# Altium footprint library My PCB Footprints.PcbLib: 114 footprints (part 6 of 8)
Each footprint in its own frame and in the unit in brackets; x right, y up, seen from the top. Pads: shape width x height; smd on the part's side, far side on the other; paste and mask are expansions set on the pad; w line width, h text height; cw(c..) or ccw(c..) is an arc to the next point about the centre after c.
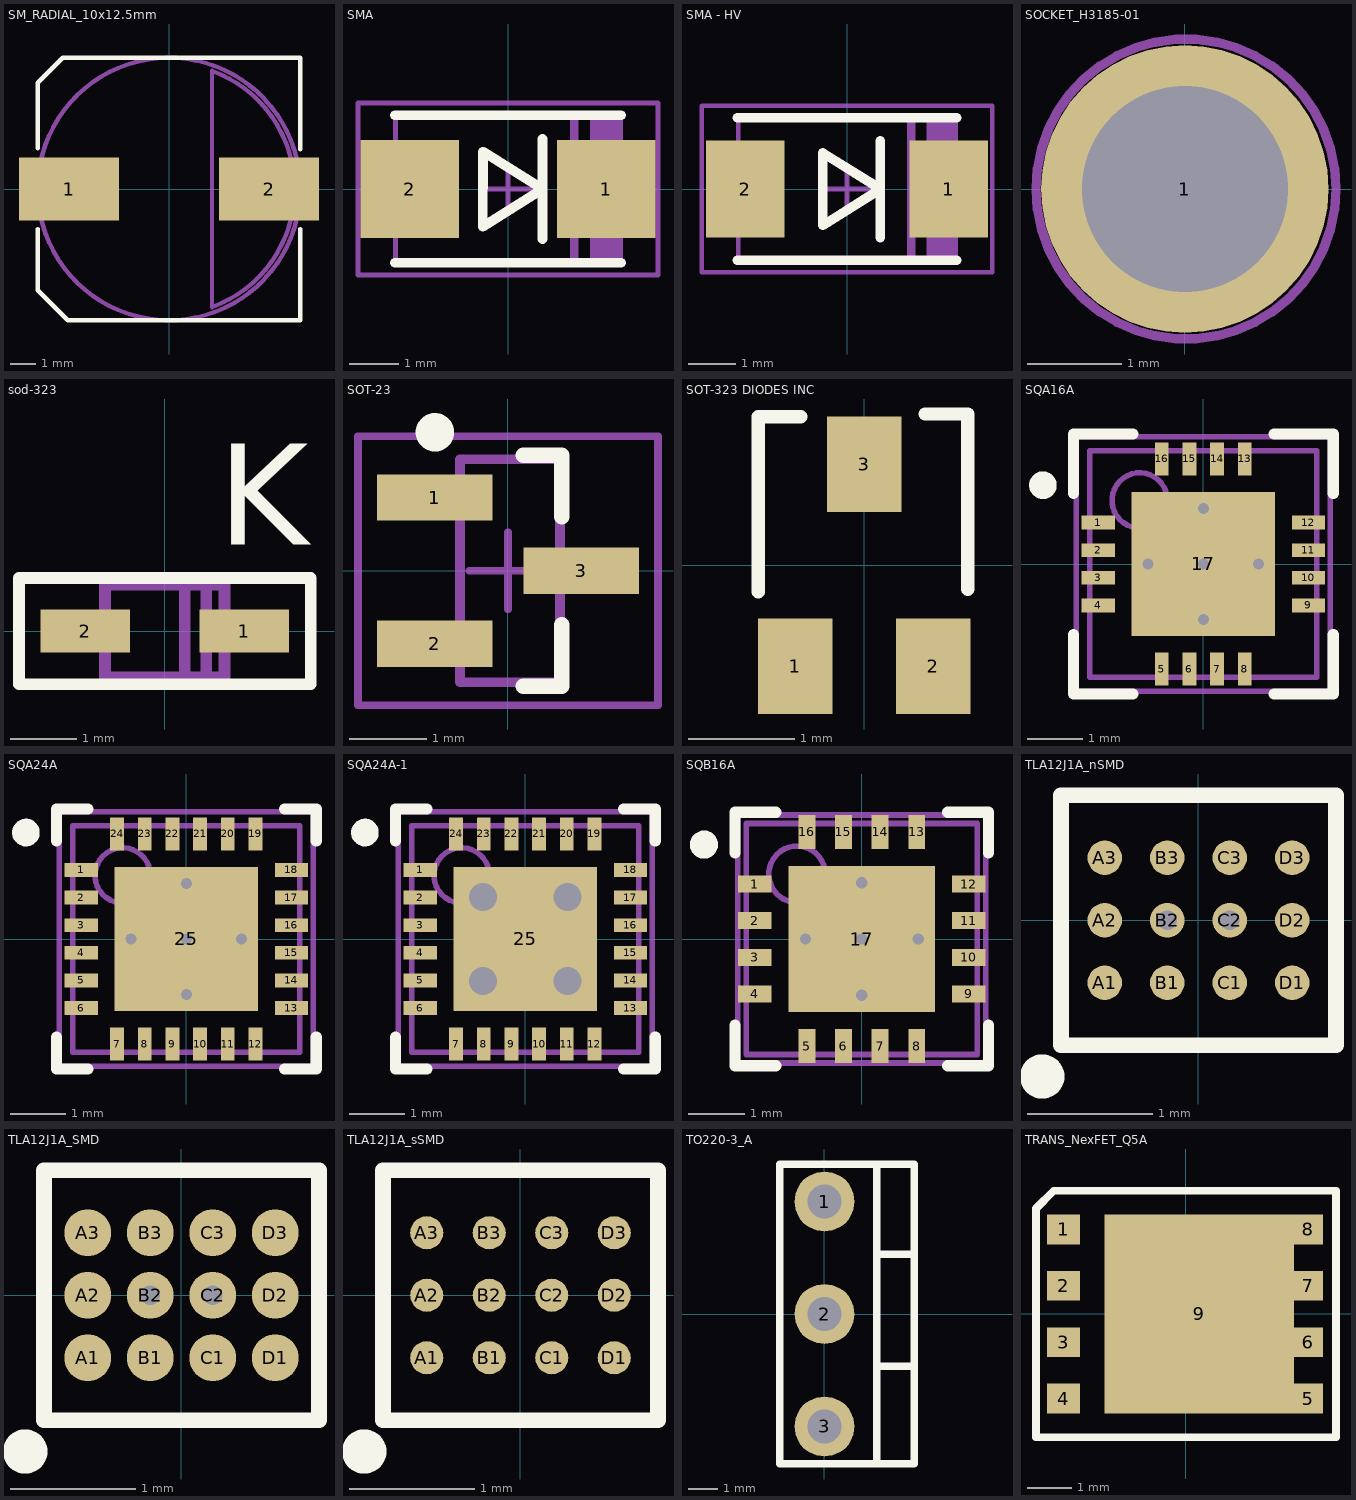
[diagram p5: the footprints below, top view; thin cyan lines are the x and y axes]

## SM_RADIAL_10x12.5mm [mm] "Suncon 10x12.5"
height 12.5
pads (2):
  rect 4x2.5 smd: 1(-4,0) 2(4,0)
Top Overlay:
  lines w0.178: -5.25,-1.6 -5.25,-4.046 -4.046,-5.25 5.25,-5.25 5.25,-1.6 ; -5.25,1.624 -5.25,4.25 -4.25,5.25 5.25,5.25 5.25,1.597
Mechanical 5:
  text ".Designator" at -1.524,-0.508 h1.02
Mechanical 13:
  circle w0.178: c0,0 r5.25
  lines w0.178: 1.72,-4.725 ccw(c0,0) 1.72,4.725 1.72,-4.725
3D body: height 1, standoff 0, extent -5.251,-5.251 5.251,5.251
3D body: height 12.5, standoff 1, extent -5.261,-5.261 5.261,5.261
3D body: height 10.5, standoff 10.4, extent 1.719,-4.726 5.039,4.726

## SMA [mm] "Molded Diode, 2-Leads, Body 4.3x2.6mm, IPC Medium Density, based on OnSemi component dimensions and land pattern"
height 2.27
pads (2):
  rect 2x2 smd: 1(2,0) 2(-2,0)
Top Overlay:
  lines w0.2: -2.3,-1.5 2.3,-1.5 ; -2.3,1.5 2.3,1.5 ; 0.698,-0.004 -0.512,-0.766 -0.507,0.758 0.698,0.006
  lines w0.203: 0.698,-1.022 0.698,1.016
Mechanical 5:
  text ".designator" at -0.927,-0.518 h1.02
Mechanical 13:
  rectangle: 1.67,-1.46 2.285,1.46
  lines w0.1: -2.285,-1.46 2.285,-1.46 2.285,1.46 -2.285,1.46 -2.285,-1.46
  lines w0.178: 1.346,-1.46 1.346,1.46 ; 1.905,-1.46 1.905,1.46
Mechanical 15:
  lines w0.1: -0.5,0 0.5,0 ; 0,-0.5 0,0.5 ; -3.05,-1.75 3.05,-1.75 3.05,1.75 -3.05,1.75 -3.05,-1.75
3D body: height 2.27, standoff 0, extent -2.285,-1.46 2.285,1.46
3D body: height 2.27, standoff 2.2, extent 1.347,-1.459 1.904,1.459

## SMA - HV [mil] "Molded Diode, 2-Leads, Body 4.3x2.6mm. Based on STTH1R06 footprint dimensions and land pattern for 600V."
height 89.37
pads (2):
  rect 65x80 smd: 1(84,0) 2(-84,0)
Top Overlay:
  lines w7.87: -90.55,-59.06 90.55,-59.06 ; -90.55,59.06 90.55,59.06 ; 27.48,-0.15 -20.16,-30.16 -19.97,29.85 27.48,0.22
  lines w8: 27.48,-40.22 27.48,40
Mechanical 5:
  text ".designator" at -36.5,-20.4 h40
Mechanical 13:
  rectangle: 65.76,-57.48 89.96,57.48
  lines w3.94: -89.96,-57.48 -89.96,57.48 89.96,57.48 89.96,-57.48 -89.96,-57.48
  lines w7: 53,-57.48 53,57.48 ; 75,-57.48 75,57.48
Mechanical 15:
  lines w3.94: -19.69,0 19.68,0 ; 0,-19.68 0,19.69 ; -120.08,-68.9 -120.08,68.9 120.08,68.9 120.08,-68.9 -120.08,-68.9
3D body: height 89.37, standoff 86.61, extent 53.02,-57.46 74.98,57.46
3D body: height 89.37, standoff 0, extent -89.96,-57.48 89.96,57.48

## SOCKET_H3185-01 [mil] "Socket pin, 1 mm Diameter"
height 39.37
pads (1):
  round 120 hole 86: 1(0,0)
Mechanical 5:
  circle w3.94: c0.5,0 r62.6
  text ".Designator" at -37,-10 h20
3D body: height 39.37, standoff -196.85, extent -62.1,-62.47 62.6,62.48

## sod-323 [mm] "Diodes Inc recommended land pattern"
height 1.5
pads (2):
  rect 1.35x0.65 smd: 1(1.2,0) 2(-1.2,0)
Top Overlay:
  lines w0.178: -2.2,-0.8 0,-0.8 2.2,-0.8 2.2,0 2.2,0.8 0,0.8 -2.2,0.8 -2.2,0 -2.2,-0.8
  text "K" at 0.8,1.3 h1.52
Mechanical 5:
  text ".Designator" at -1.524,-0.508 h1.02
Mechanical 13:
  lines w0.178: 0.3,-0.701 0.3,0.699 ; 0.625,-0.701 0.625,0.699 ; -0.902,-0.701 0.898,-0.701 0.898,0.699 -0.902,0.699 -0.902,-0.701
3D body: height 1.5, standoff 0, extent -0.901,-0.701 0.898,0.698
3D body: height 1.5, standoff 1.5, extent 0.301,-0.701 0.624,0.698

## SOT-23 [mm] "SOT23, 3-Leads, Body 2.9x1.3mm, Pitch 0.95mm, Lead Span 2.5mm, IPC Medium Density"
height 1.1
pads (3):
  rect 1.5x0.6 smd: 1(-0.95,0.95) 2(-0.95,-0.95) 3(0.95,0)
Top Overlay:
  circle w0.25: c-0.95,1.8 r0.125
  lines w0.2: 0.2,-1.5 0.7,-1.5 0.7,-0.7 ; 0.2,1.5 0.7,1.5 0.7,0.7
Mechanical 5:
  lines w0.127: -1.16,-1.15 -0.625,-1.15 -0.625,-1.45 0.675,-1.45 0.675,-0.2 1.21,-0.2 1.21,0.2 0.675,0.2 0.675,1.45 -0.625,1.45 -0.625,1.15 -1.16,1.15 -1.16,0.75 -0.625,0.75 -0.625,-0.75 -1.16,-0.75 -1.16,-1.15
  text ".Designator" at -0.175,1.225 h0.64
Mechanical 15:
  lines w0.1: -0.5,0 0.5,0 ; 0,-0.5 0,0.5 ; -1.95,-1.75 -1.95,1.75 1.95,1.75 1.95,-1.75 -1.95,-1.75
3D body: height 1, standoff 0, extent -1.16,-1.45 1.21,1.45

## SOT-323 DIODES INC [mm] "SOT-323 DIODES INC"
height 1.016
pads (4):
  round 0.25 on Top Overlay: 0(-1.3,-0.95)
  rect 0.7x0.9 smd: 1(-0.65,-0.95) 2(0.65,-0.95) 3(0,0.95)
Top Overlay:
  lines w0.127: -1,-0.25 -1,1.397 -0.6,1.397 ; 0.575,1.425 0.975,1.425 0.975,-0.225
Mechanical 5:
  text ".Designator" at 0,0 h1.52
3D body: height 1, standoff 0, extent -1,-1.45 0.975,1.5

## SQA16A [mm] "QFN, 16-Leads, Body 4x4mm, Pitch 0.5mm, NSC Recommended"
height 0.8
pads (17):
  rect 0.6x0.25 smd paste-0.125 mask+0.051: 1(-1.9,0.75) 2(-1.9,0.25) 3(-1.9,-0.25) 4(-1.9,-0.75) 9(1.9,-0.75) 10(1.9,-0.25) 11(1.9,0.25) 12(1.9,0.75)
  rect 0.25x0.6 smd paste-0.125 mask+0.051: 5(-0.75,-1.9) 6(-0.25,-1.9) 7(0.25,-1.9) 8(0.75,-1.9) 13(0.75,1.9) 14(0.25,1.9) 15(-0.25,1.9) 16(-0.75,1.9)
  rect 2.6x2.6 smd paste-1.3 mask+0.051: 17(0,0)
via 0,0 diameter 0.5 hole 0.2
via 1,0 diameter 0.5 hole 0.2
via -1,0 diameter 0.5 hole 0.2
via 0,1 diameter 0.5 hole 0.2
via 0,-1 diameter 0.5 hole 0.2
Top Overlay:
  circle w0.25: c-2.9,1.425 r0.125
  lines w0.2: -2.35,-1.275 -2.35,-2.35 -1.275,-2.35 ; -2.35,1.275 -2.35,2.35 -1.275,2.35 ; 1.275,-2.35 2.35,-2.35 2.35,-1.275 ; 1.275,2.35 2.35,2.35 2.35,1.275
Top Paste:
  region: -0.625,-2.4 -0.625,-1.7 -0.875,-1.7 -0.875,-2.4
  region: -0.125,-2.4 -0.125,-1.7 -0.375,-1.7 -0.375,-2.4
  region: 0.375,-2.4 0.375,-1.7 0.125,-1.7 0.125,-2.4
  region: 0.875,-2.4 0.875,-1.7 0.625,-1.7 0.625,-2.4
  region: 0.625,2.4 0.625,1.7 0.875,1.7 0.875,2.4
  region: 0.125,2.4 0.125,1.7 0.375,1.7 0.375,2.4
  region: -0.375,2.4 -0.375,1.7 -0.125,1.7 -0.125,2.4
  region: -0.875,2.4 -0.875,1.7 -0.625,1.7 -0.625,2.4
  region: 2.4,-0.625 1.7,-0.625 1.7,-0.875 2.4,-0.875
  region: 2.4,-0.125 1.7,-0.125 1.7,-0.375 2.4,-0.375
  region: 2.4,0.375 1.7,0.375 1.7,0.125 2.4,0.125
  region: 2.4,0.875 1.7,0.875 1.7,0.625 2.4,0.625
  rectangle: -2.4,-0.875 -1.7,-0.625
  rectangle: -2.4,-0.375 -1.7,-0.125
  rectangle: -2.4,0.125 -1.7,0.375
  rectangle: -2.4,0.625 -1.7,0.875
  rectangle: 0.1,0.1 1.2,1.2
  region: -0.1,1.2 -1.2,1.2 -1.2,0.1 -0.1,0.1
  region: -0.1,-0.1 -1.2,-0.1 -1.2,-1.2 -0.1,-1.2
  rectangle: 0.1,-1.2 1.2,-0.1
Mechanical 5:
  text ".Designator" at -1.524,-0.508 h1.02
Mechanical 13:
  circle w0.1: c-1.15,1.15 r0.5
  lines w0.1: -2.05,-2.05 2.05,-2.05 2.05,2.05 -2.05,2.05 -2.05,-2.05
Mechanical 15:
  lines w0.1: -0.5,0 0.5,0 ; 0,-0.5 0,0.5 ; -2.3,-2.3 2.3,-2.3 2.3,2.3 -2.3,2.3 -2.3,-2.3
3D body: height 0.8, standoff 0, extent -2.05,-2.05 2.05,2.05

## SQA24A [mm] "QFN, 24-Leads, Body 4x4mm, Pitch 0.5mm, NSC Recommended"
height 0.8
pads (25):
  rect 0.6x0.25 smd paste-0.125 mask+0.051: 1(-1.9,1.25) 2(-1.9,0.75) 3(-1.9,0.25) 4(-1.9,-0.25) 5(-1.9,-0.75) 6(-1.9,-1.25) 13(1.9,-1.25) 14(1.9,-0.75) 15(1.9,-0.25) 16(1.9,0.25) 17(1.9,0.75) 18(1.9,1.25)
  rect 0.25x0.6 smd paste-0.125 mask+0.051: 7(-1.25,-1.9) 8(-0.75,-1.9) 9(-0.25,-1.9) 10(0.25,-1.9) 11(0.75,-1.9) 12(1.25,-1.9) 19(1.25,1.9) 20(0.75,1.9) 21(0.25,1.9) 22(-0.25,1.9) 23(-0.75,1.9) 24(-1.25,1.9)
  rect 2.6x2.6 smd paste-1.3 mask+0.051: 25(0,0)
via 0,0 diameter 0.5 hole 0.2
via 1,0 diameter 0.5 hole 0.2
via -1,0 diameter 0.5 hole 0.2
via 0,1 diameter 0.5 hole 0.2
via 0,-1 diameter 0.5 hole 0.2
Top Overlay:
  circle w0.25: c-2.9,1.925 r0.125
  lines w0.2: -2.35,-1.775 -2.35,-2.35 -1.775,-2.35 ; -2.35,1.775 -2.35,2.35 -1.775,2.35 ; 1.775,-2.35 2.35,-2.35 2.35,-1.775 ; 1.775,2.35 2.35,2.35 2.35,1.775
Top Paste:
  region: 1.125,2.4 1.125,1.7 1.375,1.7 1.375,2.4
  region: 0.625,2.4 0.625,1.7 0.875,1.7 0.875,2.4
  region: 0.125,2.4 0.125,1.7 0.375,1.7 0.375,2.4
  region: -0.375,2.4 -0.375,1.7 -0.125,1.7 -0.125,2.4
  region: -0.875,2.4 -0.875,1.7 -0.625,1.7 -0.625,2.4
  region: -1.375,2.4 -1.375,1.7 -1.125,1.7 -1.125,2.4
  region: 2.4,-1.125 1.7,-1.125 1.7,-1.375 2.4,-1.375
  region: 2.4,-0.625 1.7,-0.625 1.7,-0.875 2.4,-0.875
  region: 2.4,-0.125 1.7,-0.125 1.7,-0.375 2.4,-0.375
  region: 2.4,0.375 1.7,0.375 1.7,0.125 2.4,0.125
  region: 2.4,0.875 1.7,0.875 1.7,0.625 2.4,0.625
  region: 2.4,1.375 1.7,1.375 1.7,1.125 2.4,1.125
  region: -1.125,-2.4 -1.125,-1.7 -1.375,-1.7 -1.375,-2.4
  region: -0.625,-2.4 -0.625,-1.7 -0.875,-1.7 -0.875,-2.4
  region: -0.125,-2.4 -0.125,-1.7 -0.375,-1.7 -0.375,-2.4
  region: 0.375,-2.4 0.375,-1.7 0.125,-1.7 0.125,-2.4
  region: 0.875,-2.4 0.875,-1.7 0.625,-1.7 0.625,-2.4
  region: 1.375,-2.4 1.375,-1.7 1.125,-1.7 1.125,-2.4
  rectangle: -2.4,-1.375 -1.7,-1.125
  rectangle: -2.4,-0.875 -1.7,-0.625
  rectangle: -2.4,-0.375 -1.7,-0.125
  rectangle: -2.4,0.125 -1.7,0.375
  rectangle: -2.4,0.625 -1.7,0.875
  rectangle: -2.4,1.125 -1.7,1.375
  rectangle: 0.1,-1.2 1.2,-0.1
  region: -0.1,-0.1 -1.2,-0.1 -1.2,-1.2 -0.1,-1.2
  region: -0.1,1.2 -1.2,1.2 -1.2,0.1 -0.1,0.1
  rectangle: 0.1,0.1 1.2,1.2
Mechanical 5:
  text ".Designator" at -1.524,-0.508 h1.02
Mechanical 13:
  circle w0.1: c-1.15,1.15 r0.5
  lines w0.1: -2.05,-2.05 -2.05,2.05 2.05,2.05 2.05,-2.05 -2.05,-2.05
Mechanical 15:
  lines w0.1: -0.5,0 0.5,0 ; 0,-0.5 0,0.5 ; -2.3,-2.3 -2.3,2.3 2.3,2.3 2.3,-2.3 -2.3,-2.3
3D body: height 0.8, standoff 0, extent -2.05,-2.05 2.05,2.05

## SQA24A-1 [mm] "QFN, 24-Leads, Body 4x4mm, Pitch 0.5mm, 4 x 20mil vias"
height 0.8
pads (25):
  rect 0.6x0.25 smd paste-0.125 mask+0.051: 1(-1.9,1.25) 2(-1.9,0.75) 3(-1.9,0.25) 4(-1.9,-0.25) 5(-1.9,-0.75) 6(-1.9,-1.25) 13(1.9,-1.25) 14(1.9,-0.75) 15(1.9,-0.25) 16(1.9,0.25) 17(1.9,0.75) 18(1.9,1.25)
  rect 0.25x0.6 smd paste-0.125 mask+0.051: 7(-1.25,-1.9) 8(-0.75,-1.9) 9(-0.25,-1.9) 10(0.25,-1.9) 11(0.75,-1.9) 12(1.25,-1.9) 19(1.25,1.9) 20(0.75,1.9) 21(0.25,1.9) 22(-0.25,1.9) 23(-0.75,1.9) 24(-1.25,1.9)
  rect 2.6x2.6 smd paste-1.3 mask+0.051: 25(0,0)
via -0.762,-0.762 diameter 0.965 hole 0.508
via 0.762,0.762 diameter 0.965 hole 0.508
via -0.762,0.762 diameter 0.965 hole 0.508
via 0.762,-0.762 diameter 0.965 hole 0.508
Top Overlay:
  circle w0.25: c-2.9,1.925 r0.125
  lines w0.2: -2.35,-1.775 -2.35,-2.35 -1.775,-2.35 ; -2.35,1.775 -2.35,2.35 -1.775,2.35 ; 1.775,-2.35 2.35,-2.35 2.35,-1.775 ; 1.775,2.35 2.35,2.35 2.35,1.775
Top Paste:
  region: 1.125,2.4 1.125,1.7 1.375,1.7 1.375,2.4
  region: 0.625,2.4 0.625,1.7 0.875,1.7 0.875,2.4
  region: 0.125,2.4 0.125,1.7 0.375,1.7 0.375,2.4
  region: -0.375,2.4 -0.375,1.7 -0.125,1.7 -0.125,2.4
  region: -0.875,2.4 -0.875,1.7 -0.625,1.7 -0.625,2.4
  region: -1.375,2.4 -1.375,1.7 -1.125,1.7 -1.125,2.4
  region: 2.4,-1.125 1.7,-1.125 1.7,-1.375 2.4,-1.375
  region: 2.4,-0.625 1.7,-0.625 1.7,-0.875 2.4,-0.875
  region: 2.4,-0.125 1.7,-0.125 1.7,-0.375 2.4,-0.375
  region: 2.4,0.375 1.7,0.375 1.7,0.125 2.4,0.125
  region: 2.4,0.875 1.7,0.875 1.7,0.625 2.4,0.625
  region: 2.4,1.375 1.7,1.375 1.7,1.125 2.4,1.125
  region: -1.125,-2.4 -1.125,-1.7 -1.375,-1.7 -1.375,-2.4
  region: -0.625,-2.4 -0.625,-1.7 -0.875,-1.7 -0.875,-2.4
  region: -0.125,-2.4 -0.125,-1.7 -0.375,-1.7 -0.375,-2.4
  region: 0.375,-2.4 0.375,-1.7 0.125,-1.7 0.125,-2.4
  region: 0.875,-2.4 0.875,-1.7 0.625,-1.7 0.625,-2.4
  region: 1.375,-2.4 1.375,-1.7 1.125,-1.7 1.125,-2.4
  rectangle: -2.4,-1.375 -1.7,-1.125
  rectangle: -2.4,-0.875 -1.7,-0.625
  rectangle: -2.4,-0.375 -1.7,-0.125
  rectangle: -2.4,0.125 -1.7,0.375
  rectangle: -2.4,0.625 -1.7,0.875
  rectangle: -2.4,1.125 -1.7,1.375
  rectangle: 0.1,-1.2 1.2,-0.1
  region: -0.1,-0.1 -1.2,-0.1 -1.2,-1.2 -0.1,-1.2
  region: -0.1,1.2 -1.2,1.2 -1.2,0.1 -0.1,0.1
  rectangle: 0.1,0.1 1.2,1.2
Mechanical 5:
  text ".Designator" at -1.524,-0.508 h1.02
Mechanical 13:
  circle w0.1: c-1.15,1.15 r0.5
  lines w0.1: -2.05,-2.05 -2.05,2.05 2.05,2.05 2.05,-2.05 -2.05,-2.05
Mechanical 15:
  lines w0.1: -0.5,0 0.5,0 ; 0,-0.5 0,0.5 ; -2.3,-2.3 -2.3,2.3 2.3,2.3 2.3,-2.3 -2.3,-2.3
3D body: height 0.8, standoff 0, extent -2.05,-2.05 2.05,2.05

## SQB16A [mm] "QFN, 16-Leads, Body 4x4mm, Pitch 0.65mm, NSC Recommended"
height 0.8
pads (17):
  rect 0.6x0.3 smd paste-0.15 mask+0.051: 1(-1.9,0.975) 2(-1.9,0.325) 3(-1.9,-0.325) 4(-1.9,-0.975) 9(1.9,-0.975) 10(1.9,-0.325) 11(1.9,0.325) 12(1.9,0.975)
  rect 0.3x0.6 smd paste-0.15 mask+0.051: 5(-0.975,-1.9) 6(-0.325,-1.9) 7(0.325,-1.9) 8(0.975,-1.9) 13(0.975,1.9) 14(0.325,1.9) 15(-0.325,1.9) 16(-0.975,1.9)
  rect 2.6x2.6 smd paste-1.3 mask+0.051: 17(0,0)
via 0,0 diameter 0.5 hole 0.2
via 1,0 diameter 0.5 hole 0.2
via -1,0 diameter 0.5 hole 0.2
via 0,1 diameter 0.5 hole 0.2
via 0,-1 diameter 0.5 hole 0.2
Top Overlay:
  circle w0.25: c-2.8,1.675 r0.125
  lines w0.2: -2.25,-1.525 -2.25,-2.25 -1.525,-2.25 ; -2.25,1.525 -2.25,2.25 -1.525,2.25 ; 1.525,-2.25 2.25,-2.25 2.25,-1.525 ; 1.525,2.25 2.25,2.25 2.25,1.525
Top Paste:
  rectangle: -2.4,0.825 -1.7,1.125
  rectangle: -2.4,0.175 -1.7,0.475
  rectangle: -2.4,-0.475 -1.7,-0.175
  rectangle: -2.4,-1.125 -1.7,-0.825
  region: 1.125,-2.4 1.125,-1.7 0.825,-1.7 0.825,-2.4
  region: 0.475,-2.4 0.475,-1.7 0.175,-1.7 0.175,-2.4
  region: -0.175,-2.4 -0.175,-1.7 -0.475,-1.7 -0.475,-2.4
  region: -0.825,-2.4 -0.825,-1.7 -1.125,-1.7 -1.125,-2.4
  region: 2.4,1.125 1.7,1.125 1.7,0.825 2.4,0.825
  region: 2.4,0.475 1.7,0.475 1.7,0.175 2.4,0.175
  region: 2.4,-0.175 1.7,-0.175 1.7,-0.475 2.4,-0.475
  region: 2.4,-0.825 1.7,-0.825 1.7,-1.125 2.4,-1.125
  region: -1.125,2.4 -1.125,1.7 -0.825,1.7 -0.825,2.4
  region: -0.475,2.4 -0.475,1.7 -0.175,1.7 -0.175,2.4
  region: 0.175,2.4 0.175,1.7 0.475,1.7 0.475,2.4
  region: 0.825,2.4 0.825,1.7 1.125,1.7 1.125,2.4
  rectangle: 0.1,0.1 1.2,1.2
  region: -0.1,1.2 -1.2,1.2 -1.2,0.1 -0.1,0.1
  region: -0.1,-0.1 -1.2,-0.1 -1.2,-1.2 -0.1,-1.2
  rectangle: 0.1,-1.2 1.2,-0.1
Mechanical 5:
  text ".Designator" at -1.524,-0.508 h1.02
Mechanical 13:
  circle w0.1: c-1.15,1.15 r0.5
  lines w0.1: -2.05,-2.05 -2.05,2.05 2.05,2.05 2.05,-2.05 -2.05,-2.05
Mechanical 15:
  lines w0.1: -0.5,0 0.5,0 ; 0,-0.5 0,0.5 ; -2.2,-2.2 -2.2,2.2 2.2,2.2 2.2,-2.2 -2.2,-2.2
3D body: height 0.8, standoff 0, extent -2.05,-2.05 2.05,2.05

## TLA12J1A_nSMD [mm] "12 Bump µSMD,  non-Solder Mask Defined, 2 x 2mm"
height 0.675
pads (12):
  round 0.275 smd: A1(-0.75,-0.5) A2(-0.75,0) A3(-0.75,0.5) B1(-0.25,-0.5) B2(-0.25,0) B3(-0.25,0.5) C1(0.25,-0.5) C2(0.25,0) C3(0.25,0.5) D1(0.75,-0.5) D2(0.75,0) D3(0.75,0.5)
via 0.25,0 diameter 0.275 hole 0.152
via -0.25,0 diameter 0.275 hole 0.152
Top Overlay:
  circle w0.254: c-1.25,-1.25 r0.05
  lines w0.127: -1.1,-1 1.1,-1 1.1,1 -1.1,1 -1.1,-1
Mechanical 5:
  text ".Designator" at -1.35,-0.35 h1.02
3D body: height 0.67, standoff 0, extent -1,-0.9 1,0.9

## TLA12J1A_SMD [mm] "12 Bump µSMD,  Solder Mask Defined, 2 x 2mm"
height 0.675
pads (12):
  round 0.375 smd paste-0.051 mask-0.051: A1(-0.75,-0.5) A2(-0.75,0) A3(-0.75,0.5) B1(-0.25,-0.5) B2(-0.25,0) B3(-0.25,0.5) C1(0.25,-0.5) C2(0.25,0) C3(0.25,0.5) D1(0.75,-0.5) D2(0.75,0) D3(0.75,0.5)
via -0.25,0 diameter 0.275 hole 0.152
via 0.25,0 diameter 0.275 hole 0.152
Top Overlay:
  circle w0.254: c-1.25,-1.25 r0.05
  lines w0.127: -1.1,-1 1.1,-1 1.1,1 -1.1,1 -1.1,-1
Mechanical 5:
  text ".Designator" at -1.35,-0.35 h1.02
3D body: height 0.67, standoff 0, extent -1,-0.9 1,0.9

## TLA12J1A_sSMD [mm] "12 Bump µSMD,  Solder Mask Defined, 2 x 2mm"
height 0.675
pads (12):
  round 0.265 smd paste-0.051 mask-0.051: A1(-0.75,-0.5) A2(-0.75,0) A3(-0.75,0.5) B1(-0.25,-0.5) B2(-0.25,0) B3(-0.25,0.5) C1(0.25,-0.5) C2(0.25,0) C3(0.25,0.5) D1(0.75,-0.5) D2(0.75,0) D3(0.75,0.5)
Top Overlay:
  circle w0.254: c-1.25,-1.25 r0.05
  lines w0.127: -1.1,-1 -1.1,1 1.1,1 1.1,-1 -1.1,-1
Mechanical 5:
  text ".Designator" at -1.35,-0.35 h1.02
3D body: height 0.67, standoff 0, extent -1,-0.9 1,0.9

## TO220-3_A [mil]
pads (3):
  round 80 hole 45: 1(0,150) 2(0,0) 3(0,-150)
Top Overlay:
  lines w10: 70,-200 70,200 ; 70,-70 120,-70 ; 70,80 120,80 ; -60,-200 120,-200 120,200 -60,200 -60,-200

## TRANS_NexFET_Q5A [mm] "TI recommended land pattern (nominal) M0139-01"
height 1.1
pads (9):
  rect 0.75x0.675 smd paste-0.1 mask+0.051: 1(-2.776,1.917) 2(-2.776,0.639) 3(-2.776,-0.639) 4(-2.776,-1.917)
  rect 0.655x0.675 smd paste-0.1 mask+0.051: 5(2.776,-1.917) 6(2.776,-0.639) 7(2.776,0.639) 8(2.776,1.917)
  rect 4.295x4.51 smd paste-2.2 mask+0.051: 9(0.301,0)
Top Overlay:
  lines w0.178: -3.4,-2.795 -3.4,0 -3.4,2.39 -2.995,2.795 0,2.795 3.4,2.795 3.4,0 3.4,-2.795 0,-2.795 -3.4,-2.795
Top Paste:
  region: -1.412,-0.31 -1.412,-1.88 -0.177,-1.88 -0.177,-0.31
  region: -1.412,0.31 -1.412,1.88 -0.177,1.88 -0.177,0.31
  region: 0.323,-0.31 0.323,-1.88 1.908,-1.88 1.908,-0.31
  region: 0.323,0.31 0.323,1.88 1.908,1.88 1.908,0.31
Mechanical 5:
  text ".Designator" at -1.529,-0.508 h1.02
3D body: height 1.11, standoff 0, extent -3.05,-2.5 3.05,2.5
